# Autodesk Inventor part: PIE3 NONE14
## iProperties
Shininess: 64.0
Length Units: 11269
Angle Units: 11279
Time Units: 11290
Mass Units: 11286
Length Display Precision: 3
Angle Display Precision: 2
Compacted: True
Part Number: PIE3 NONE14
Document SubType Name: Modeling
Created: 2004-08
Designer: John Blackburn
Manufacturer: Standard
Standards Organization: Custom
Density: 0.0
Volumn: 0.0
Area: 0.0
PropertySet Name: Model Information
Control State: 0
Master: False
Checked Out: False
Author: John Blackburn
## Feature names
1. Erst1
